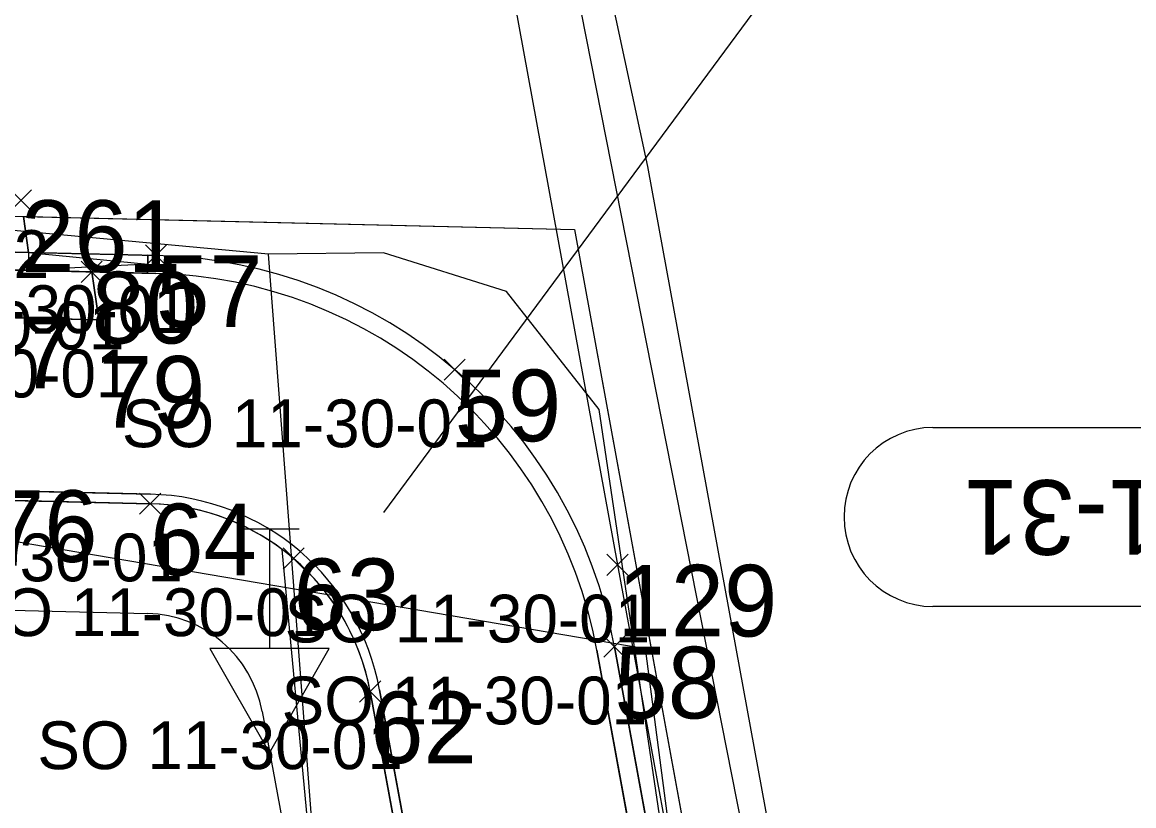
# Model space of a CAD drawing. Extents: x -728800 to -728100, y -1073200 to -1072700.
# Drawn here: x -728515.93 to -728506.62, y -1073033.86 to -1073027.29 of the extents above; entities that cross this region are included whole.
import ezdxf

# ---------------------------------------------------------------- set-up
doc = ezdxf.new("R2010")
doc.units = 0
for name, color, linetype in [('_NOR-návrh tenká', 7, 'Continuous'), ('_NOR-VDZ', 7, 'Continuous'), ('_NOR-šraf_+12', 7, 'Continuous'), ('_NOR-šraf_+6', 7, 'Continuous'), ('_NOR-šraf_bezbariéra', 7, 'Continuous'), ('_NOR-šraf_chodník', 7, 'Continuous'), ('_NOR-šraf_varovný pás', 7, 'Continuous'), ('_NOR-šraf_vozovka', 7, 'Continuous'), ('_NOR-šraf_zeleň', 7, 'Continuous'), ('A1_OBVOD Spravy železnic', 7, 'Continuous'), ('A2_OBVOD STAVBY', 7, 'Continuous'), ('B1_body_poloha', 7, 'Continuous'), ('B2_body_číslo', 7, 'Continuous'), ('B3_body_popiska', 7, 'Continuous'), ('B6_JŽM', 7, 'Continuous'), ('KTA_členění PS a SO', 7, 'Continuous'), ('ZA_02_Dočasný_do_1_roku', 7, 'Continuous')]:
    doc.layers.add(name, color=color, linetype=linetype)

msp = doc.modelspace()

# ---------------------------------------------------------------- linework, layer by layer
at = {"layer": '_NOR-návrh tenká'}
for p, q in [((-728515.8757, -1073029.2224), (-728515.8793, -1073029.3724)), ((-728515.8757, -1073029.2224), (-728514.8778, -1073029.3212)), ((-728514.8796, -1073029.3961), (-728514.876, -1073029.2462)), ((-728514.8778, -1073029.3212), (-728515.8793, -1073029.3724)), ((-728515.3467, -1073029.385), (-728515.2881, -1073029.7865))]:
    msp.add_line(p, q, dxfattribs=at)
for points in [[(-728520.806, -1073029.1053), (-728520.7989, -1073028.8054), (-728511.3038, -1073029.0309), (-728510.0672, -1073035.7772)], [(-728520.806, -1073029.1053), (-728514.8077, -1073029.2478)], [(-728520.8096, -1073029.2553), (-728514.8113, -1073029.3978)], [(-728514.8571, -1073031.3272), (-728517.7058, -1073031.2595), (-728517.9887, -1073029.3223)], [(-728514.8552, -1073031.2472), (-728517.6364, -1073031.1812), (-728517.9075, -1073029.3242)], [(-728517.8489, -1073029.7257), (-728515.2881, -1073029.7865)], [(-728510.9683, -1073032.5255), (-728510.3623, -1073035.8313)], [(-728511.1158, -1073032.5525), (-728510.5098, -1073035.8583)], [(-728512.7415, -1073034.3881), (-728513.0142, -1073032.9005)], [(-728512.6628, -1073034.3737), (-728512.9355, -1073032.8861)]]:
    msp.add_lwpolyline(points, dxfattribs=at)
for radius in [4, 3.85, 1.92, 2]:
    msp.add_arc((-728514.9027, -1073033.2467), radius, 10.38717, 88.63928, dxfattribs=at)
at = {"layer": '_NOR-VDZ'}
for points in [[(-728512.9486, -1073020.8901), (-728510.9416, -1073031.8393)], [(-728510.9416, -1073031.8393), (-728510.2148, -1073035.8042)]]:
    msp.add_lwpolyline(points, dxfattribs=at)
at = {"layer": '_NOR-šraf_+12'}
for p, q in [((-728514.876, -1073029.2462), (-728514.8778, -1073029.3212)), ((-728514.8077, -1073029.2478), (-728514.876, -1073029.2462)), ((-728514.8778, -1073029.3212), (-728514.8796, -1073029.3961)), ((-728514.8796, -1073029.3961), (-728514.8113, -1073029.3978)), ((-728510.3623, -1073035.8313), (-728510.9683, -1073032.5255)), ((-728511.1158, -1073032.5525), (-728510.5098, -1073035.8583))]:
    msp.add_line(p, q, dxfattribs=at)
for radius, end in [(4, 88.63929), (3.85, 88.63928)]:
    msp.add_arc((-728514.9027, -1073033.2467), radius, 10.38717, end, dxfattribs=at)
at = {"layer": '_NOR-šraf_+6'}
for p, q in [((-728514.8552, -1073031.2472), (-728516.1911, -1073031.2155)), ((-728517.7058, -1073031.2595), (-728514.8571, -1073031.3272)), ((-728513.0142, -1073032.9005), (-728512.7879, -1073034.1348)), ((-728512.7066, -1073034.1348), (-728512.9355, -1073032.8861))]:
    msp.add_line(p, q, dxfattribs=at)
for radius, end in [(1.92, 88.63929), (2, 88.63928)]:
    msp.add_arc((-728514.9027, -1073033.2467), radius, 10.38717, end, dxfattribs=at)
at = {"layer": '_NOR-šraf_bezbariéra'}
msp.add_lwpolyline([(-728517.904, -1073029.1742), (-728515.8757, -1073029.2224), (-728515.8793, -1073029.3724), (-728517.9075, -1073029.3242), (-728517.904, -1073029.1742), (-728517.904, -1073029.1742)], dxfattribs=at)
at = {"layer": '_NOR-šraf_chodník'}
for p, q in [((-728510.5098, -1073035.8583), (-728511.1158, -1073032.5525)), ((-728512.9355, -1073032.8861), (-728512.6628, -1073034.3737))]:
    msp.add_line(p, q, dxfattribs=at)
for points in [[(-728514.8113, -1073029.3978), (-728514.8796, -1073029.3961), (-728515.3467, -1073029.385), (-728515.2881, -1073029.7865)], [(-728515.2881, -1073029.7865), (-728516.4036, -1073029.76), (-728516.1911, -1073031.2155), (-728514.8552, -1073031.2472)]]:
    msp.add_lwpolyline(points, dxfattribs=at)
for radius in [3.85, 2]:
    msp.add_arc((-728514.9027, -1073033.2467), radius, 10.38717, 88.63928, dxfattribs=at)
at = {"layer": '_NOR-šraf_varovný pás'}
msp.add_lwpolyline([(-728517.8489, -1073029.7257), (-728517.2149, -1073029.7408), (-728516.4036, -1073029.76), (-728515.2881, -1073029.7865), (-728515.3467, -1073029.385), (-728515.8793, -1073029.3724), (-728517.9075, -1073029.3242), (-728517.8489, -1073029.7257)], dxfattribs=at)
at = {"layer": '_NOR-šraf_vozovka'}
for p, q in [((-728515.8757, -1073029.2224), (-728515.9197, -1073028.9213)), ((-728515.9197, -1073028.9213), (-728511.3038, -1073029.0309)), ((-728515.9197, -1073028.9213), (-728515.8757, -1073029.2224)), ((-728511.3038, -1073029.0309), (-728510.0672, -1073035.7772)), ((-728514.8077, -1073029.2478), (-728515.8757, -1073029.2224)), ((-728510.3623, -1073035.8313), (-728510.9683, -1073032.5255))]:
    msp.add_line(p, q, dxfattribs=at)
msp.add_lwpolyline([(-728515.8757, -1073029.2224), (-728517.904, -1073029.1742), (-728517.9479, -1073028.8731), (-728515.9197, -1073028.9213)], dxfattribs=at)
msp.add_arc((-728514.9027, -1073033.2467), 4, 10.38717, 88.63929, dxfattribs=at)
at = {"layer": '_NOR-šraf_zeleň'}
for p, q in [((-728514.8571, -1073031.3272), (-728517.7058, -1073031.2595)), ((-728513.4891, -1073034.5069), (-728513.7507, -1073031.7107)), ((-728513.4891, -1073034.5069), (-728513.7507, -1073031.7107)), ((-728518.3896, -1073032.1636), (-728514.879, -1073032.2469)), ((-728513.0142, -1073032.9005), (-728512.7879, -1073034.1348)), ((-728513.9191, -1073033.0664), (-728513.4467, -1073035.6436))]:
    msp.add_line(p, q, dxfattribs=at)
for radius, start, end in [(1.92, 53.12987, 88.63928), (1.92, 10.38717, 53.12987), (1, 10.38717, 88.63928)]:
    msp.add_arc((-728514.9027, -1073033.2467), radius, start, end, dxfattribs=at)
at = {"layer": 'A1_OBVOD Spravy železnic'}
msp.add_lwpolyline([(-728582.13, -1073004.22), (-728564.68, -1073020.02), (-728543.86, -1073026.9), (-728510.71, -1073032.54), (-728510.22, -1073036.28), (-728509.4149, -1073042.1854), (-728509.9, -1073046.86), (-728541.12, -1073039.22), (-728572.55, -1073027.78)], dxfattribs=at)
at = {"layer": 'A2_OBVOD STAVBY'}
msp.add_lwpolyline([(-728509.4552, -1073035.2336), (-728510.6892, -1073028.5017), (-728511.9326, -1073022.7067), (-728511.9855, -1073020.0018), (-728513.1567, -1073020.2167), (-728515.2549, -1073019.3795), (-728517.2156, -1073018.5898), (-728517.0958, -1073019.4415), (-728517.7271, -1073020.6847), (-728519.1997, -1073021.5604), (-728519.7796, -1073021.5967), (-728522.5314, -1073023.4081), (-728531.1593, -1073023.4373), (-728533.9967, -1073023.3407), (-728538.3859, -1073022.9665), (-728542.2911, -1073022.2874), (-728547.2961, -1073020.5858), (-728553.9655, -1073017.86)], dxfattribs=at)
at = {"layer": 'B1_body_poloha'}
for p, q in [((-728516.0274, -1073028.6976), (-728515.8506, -1073028.8744)), ((-728516.0274, -1073028.8744), (-728515.8506, -1073028.6976)), ((-728514.8961, -1073029.1594), (-728514.7193, -1073029.3362)), ((-728514.8961, -1073029.3362), (-728514.7193, -1073029.1594)), ((-728515.4354, -1073029.2966), (-728515.2586, -1073029.4734)), ((-728515.4354, -1073029.4734), (-728515.2586, -1073029.2966)), ((-728512.3944, -1073030.1156), (-728512.2176, -1073030.2924)), ((-728512.3944, -1073030.2924), (-728512.2176, -1073030.1156)), ((-728514.9455, -1073031.2388), (-728514.7687, -1073031.4156)), ((-728514.9455, -1073031.4156), (-728514.7687, -1073031.2388)), ((-728513.7444, -1073031.6976), (-728513.5676, -1073031.8744)), ((-728513.7444, -1073031.8744), (-728513.5676, -1073031.6976)), ((-728511.0304, -1073031.7506), (-728510.8536, -1073031.9274)), ((-728511.0304, -1073031.9274), (-728510.8536, -1073031.7506)), ((-728511.0564, -1073032.4366), (-728510.8796, -1073032.6134)), ((-728511.0564, -1073032.6134), (-728510.8796, -1073032.4366)), ((-728513.1024, -1073032.8116), (-728512.9256, -1073032.9884)), ((-728513.1024, -1073032.9884), (-728512.9256, -1073032.8116))]:
    msp.add_line(p, q, dxfattribs=at)
at = {"layer": 'B2_body_číslo'}
for p, q in [((-728514.808, -1073029.248), (-728514.808, -1073029.248)), ((-728515.347, -1073029.385), (-728515.347, -1073029.385)), ((-728515.288, -1073029.787), (-728515.288, -1073029.787)), ((-728512.306, -1073030.204), (-728512.306, -1073030.204)), ((-728514.857, -1073031.327), (-728514.857, -1073031.327)), ((-728513.656, -1073031.786), (-728513.656, -1073031.786)), ((-728510.942, -1073031.839), (-728510.942, -1073031.839)), ((-728510.968, -1073032.525), (-728510.968, -1073032.525)), ((-728513.014, -1073032.9), (-728513.014, -1073032.9))]:
    msp.add_line(p, q, dxfattribs=at)
at = {"layer": 'B6_JŽM'}
msp.add_line((-728513.609, -1073031.539), (-728514.109, -1073031.539), dxfattribs=at)
for points in [[(-728510.066, -1073037.464), (-728511.097, -1073030.537), (-728511.871, -1073029.55), (-728512.902, -1073029.227), (-728513.865, -1073029.238), (-728518.889, -1073028.771), (-728523.455, -1073028.329), (-728528.834, -1073028.159)], [(-728513.553, -1073040.642), (-728513.354, -1073039.355), (-728513.463, -1073034.501), (-728513.865, -1073029.238)], [(-728513.859, -1073031.539), (-728513.859, -1073032.539), (-728514.359, -1073032.539), (-728513.859, -1073033.414), (-728513.359, -1073032.539), (-728513.859, -1073032.539)]]:
    msp.add_lwpolyline(points, dxfattribs=at)
at = {"layer": 'KTA_členění PS a SO'}
msp.add_line((-728507.5477, -1073024.1576), (-728512.902, -1073031.4012), dxfattribs=at)
for points in [[(-728508.3004, -1073030.6882), (-728503.3004, -1073030.6882)], [(-728503.3004, -1073032.1882), (-728508.3004, -1073032.1882)]]:
    msp.add_lwpolyline(points, dxfattribs=at)
msp.add_arc((-728508.2945, -1073031.4382), 0.75, 90.45289, 269.54711, dxfattribs=at)
at = {"layer": 'ZA_02_Dočasný_do_1_roku'}
msp.add_lwpolyline([(-728542.3408, -1073022.4817), (-728538.4115, -1073023.1651), (-728534.0086, -1073023.5404), (-728531.1624, -1073023.6373), (-728526.8168, -1073023.6226), (-728522.4712, -1073023.6079), (-728519.714, -1073021.793), (-728519.139, -1073021.757), (-728517.575, -1073020.827), (-728516.889, -1073019.476), (-728516.9694, -1073018.9046), (-728513.1773, -1073020.4238), (-728512.1809, -1073020.241), (-728512.1322, -1073022.7298), (-728509.6065, -1073035.5175), (-728510.3267, -1073035.4653), (-728509.4149, -1073042.1854)], dxfattribs=at)

# ---------------------------------------------------------------- texts
at = {"layer": 'B2_body_číslo'}
for s, p in [('261', (-728515.939, -1073029.386)), ('57', (-728514.808, -1073029.848)), ('80', (-728515.347, -1073029.985)), ('77', (-728516.404, -1073030.36)), ('79', (-728515.288, -1073030.69)), ('59', (-728512.306, -1073030.804)), ('76', (-728516.191, -1073031.815)), ('64', (-728514.857, -1073031.927)), ('63', (-728513.656, -1073032.386)), ('129', (-728510.942, -1073032.439)), ('58', (-728510.968, -1073033.125)), ('62', (-728513.014, -1073033.5))]:
    msp.add_text(s, height=0.6, dxfattribs=at).set_placement(p)
at = {"layer": 'B3_body_popiska'}
for s, p in [('SO_11-30-02', (-728518.9155, -1073029.436)), ('SO 11-30-01', (-728517.5967, -1073029.898)), ('SO 11-30-01', (-728518.1357, -1073030.035)), ('SO 11-30-01', (-728518.0767, -1073030.437)), ('SO 11-30-01', (-728515.0947, -1073030.854)), ('SO 11-30-01', (-728517.6457, -1073031.977)), ('SO 11-30-01', (-728516.4447, -1073032.436)), ('SO 11-30-01', (-728513.7307, -1073032.489)), ('SO 11-30-01', (-728513.7567, -1073033.175)), ('SO 11-30-01', (-728515.8027, -1073033.55))]:
    msp.add_text(s, height=0.4, dxfattribs=at).set_placement(p)
at = {"layer": 'KTA_členění PS a SO'}
msp.add_text('PS 11-01-31', height=0.625, rotation=180, dxfattribs=at).set_placement((-728503.3497, -1073031.1298))

doc.saveas('drawing.dxf')
